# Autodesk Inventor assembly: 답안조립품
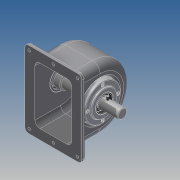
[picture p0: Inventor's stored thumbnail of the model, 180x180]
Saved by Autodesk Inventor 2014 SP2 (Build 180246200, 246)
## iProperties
Created: 2015-09
Part Number: 답안조립품
Document SubType Name: Assembly
Designer: 201-17
Author: 201-17
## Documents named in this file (14)
- C:\Users\201-17\Desktop\450907V1013\답안조립품.iam
- C:\Users\201-17\Desktop\450907V1013\본체.ipt
- C:\Users\201-17\Desktop\450907V1013\베어링 6203.ipt
- C:\Users\201-17\Desktop\450907V1013\축.ipt
- C:\Users\201-17\Desktop\450907V1013\뒤커버.ipt
- C:\Users\201-17\Desktop\450907V1013\키 - 6 x 6 x 22.ipt
- C:\Users\201-17\Desktop\450907V1013\키 - 5 x 5 x 18.ipt
- C:\Users\201-17\Desktop\450907V1013\스퍼기어.ipt
- C:\Users\201-17\Desktop\450907V1013\V-벨트풀리.ipt
- C:\Users\201-17\Desktop\450907V1013\오일 실 17 32 8.ipt
- C:\Users\201-17\Desktop\450907V1013\앞커버.ipt
- C:\Users\201-17\Desktop\450907V1013\볼트 M3 x 10.ipt
- C:\Users\201-17\Desktop\450907V1013\볼트 M3 x 8.ipt
- C:\Users\201-17\Desktop\450907V1013\멈춤나사 - M4x10.ipt
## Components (9 placed, 3 different names)
1. V-벨트풀리:1 — 각도:2
2. ISO 4762 M3 x 10:1
3. ISO 4762 M3 x 10:2
4. ISO 4762 M3 x 10:3
5. ISO 4762 M3 x 10:4
6. ISO 4762 M3 x 8:1
7. ISO 4762 M3 x 8:2
8. ISO 4762 M3 x 8:3
9. ISO 4762 M3 x 8:4
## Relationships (1: Angle 1)
- 각도:2 [Angle]: V-벨트풀리:1
